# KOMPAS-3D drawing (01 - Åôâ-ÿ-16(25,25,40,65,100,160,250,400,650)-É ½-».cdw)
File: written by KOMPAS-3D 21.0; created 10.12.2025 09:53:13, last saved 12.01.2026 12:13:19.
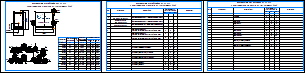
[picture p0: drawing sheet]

Sheets 1-3: A3, landscape

Document properties: Автор: RaskoAdmin; Форматы листов документа: 3xA3; Полное имя файла: \\ur38nt01\Departments\КТО\КБ ПУРДГ\Заявки\Прайс-лист на типовые шкафы ГРПШ\ПУГ-Ш-16(25,25,40,65,100,160,250,400,650)-Р л-п.cdw

Title block, sheet 1: sheet number: 1; Количество листов документа: 3; Форматы листов документа: A3; stored path: \\ur38nt01\Departments\КТО\КБ ПУРДГ\Заявки\Прайс-лист на типовые шкафы ГРПШ\ПУГ-Ш-65-Р.cdw
Title block, sheet 2: sheet number: 2
Title block, sheet 3: sheet number: 3; sheet number: 6; stored path: \\ur38nt01\Departments\КТО\КБ ПУРДГ\Заявки\Прайс-лист на типовые шкафы ГРПШ\ПУГ-Ш-65(160,250,400)-Р л-п.cdw

Views: Вид 1
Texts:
  logo-rasko-ge(1).png
  Выход
  Вход
  Ду20
  Свеча
  Пункт учета газа ПУГ-Ш Ду 50, 80, 100
  с измерительным комплексом на базе счетчика РГ-Р
  ОГНЕОПАСНО ГАЗ
  Поз.
  Условный проход
  расходомера Ду, мм
  СГ-ЭК-Р-(0,2...2,0)-
  Измерительный комплекс с ротационным счетчиком Ду80
  Измерительный комплекс с ротационным счетчиком Ду50
  Измерительный комплекс с ротационным счетчиком Ду100
  Фильтр газа ФГ Ду80
  (Оснащен индикатором перепада давления ДПД)
  Фильтр газа ФГ Ду50
  Фильтр газа ФГ Ду100
  Кран кнопочный под манометр
  Кран шаровой штуцерный Ду20
  Кран шаровый с мех.приводом Ду80
  Кран шаровый с мех.приводом Ду50
  Кран шаровый с мех.приводом Ду100
  Кран шаровый Ду50
  Кран шаровый Ду80
  Кран шаровый Ду100
  Условный
  проход Ду, мм
  Qmax,
  Диапазон
  измерений
  Qmin/Qmax
  Габаритные размеры
  А, мм
  В, мм
  Н, мм
  ПУГ-Ш-16-Р
  Манометр
  Отвод Ду50
  Отвод Ду80
  Отвод Ду100
  Фланец Ду50
  Фланец Ду80
  Фланец Ду100
  Фланец воротниковый Ду50
  Фланец воротниковый Ду80
  Фланец воротниковый Ду100
  POLYLINE_STYLE_0.18_RGB_0_0_0
  Без основной надписи.
Dimensions and other numbers on the sheet: 550; 1; 2; 3; 4; 5; 6; 7; 8; 10; 9; 50; 80; 100; -160 (250; 400)/1,6; -250 (400; 650)/1,6; 16; 0,3/16; 1800; 700; 1760; -65-Р; -40-Р; -25-Р; -100-Р; 65; 40; 25; 0,5/65; 0,5/40; 0,5/25; 0,4/100; -160-Р; 160; 0,6/160; 2100; -250-Р; 250; 1,0/250; -400-Р; 400; 1,6/400; -650-Р; 650; 2,5/650; 2300; 1000; 2000; 12; 1:20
